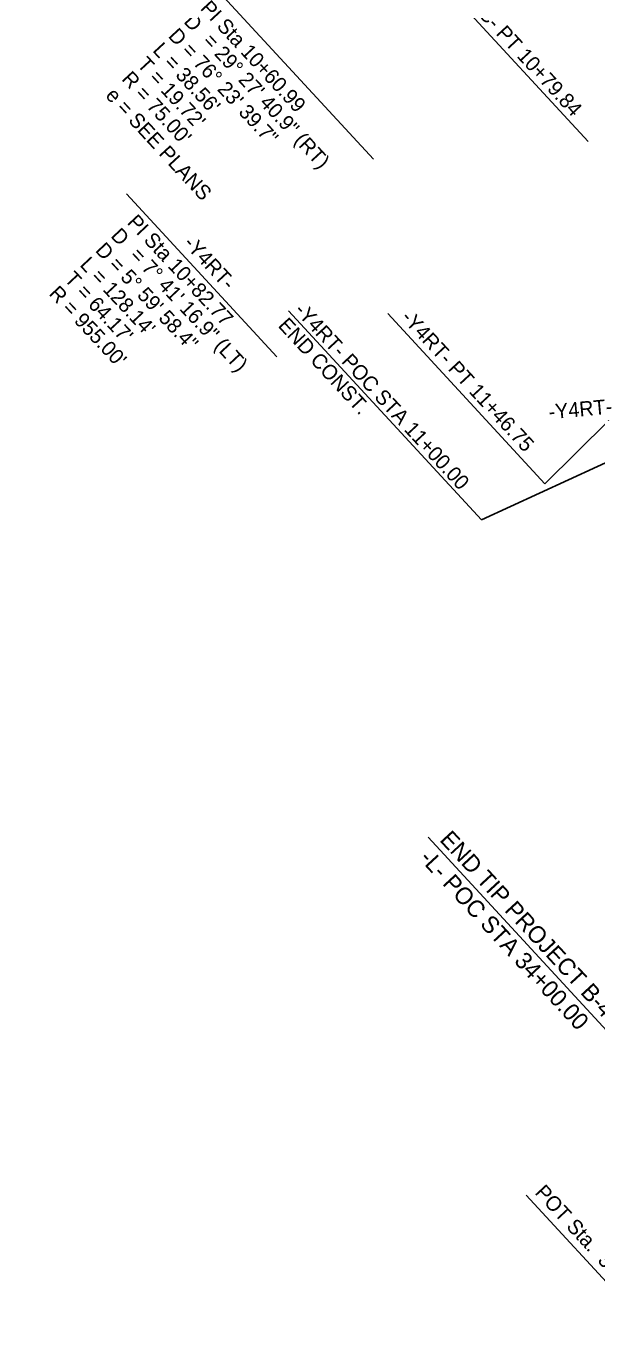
# Model space of a CAD drawing. Extents: x 1702862 to 1704514, y 793768 to 796215.
# Drawn here: x 1703564 to 1703834, y 793768 to 794386 of the extents above; entities that cross this region are included whole.
import ezdxf

# ---------------------------------------------------------------- set-up
doc = ezdxf.new("R2010")
doc.units = 0
for name, color, linetype in [('Exist Horizontal Alignment Curve and Spiral Data', 7, 'Continuous'), ('Exist Horizontal Alignment Station Label', 7, 'Continuous'), ('Prop DSN Text', 7, 'Continuous'), ('Prop EOT', 7, 'Continuous'), ('Prop Horizontal Alignment', 7, 'Continuous'), ('Prop Horizontal Alignment Curve and Spiral Data', 7, 'Continuous'), ('Prop Horizontal Alignment Direction Label', 7, 'Continuous'), ('Prop Horizontal Alignment Station Label', 7, 'Continuous'), ('Prop Lane Lines', 7, 'Continuous'), ('Prop Leader Line Medium', 7, 'Continuous')]:
    doc.layers.add(name, color=color, linetype=linetype)

msp = doc.modelspace()

# ---------------------------------------------------------------- linework, layer by layer
at = {"layer": 'Exist Horizontal Alignment Curve and Spiral Data'}
msp.add_line((1703611.73, 794306.9), (1703682.73, 794229.98), dxfattribs=at)
at = {"layer": 'Exist Horizontal Alignment Station Label'}
for p, q in [((1703735.18, 794250.31), (1703809.32, 794169.99)), ((1703809.32, 794169.99), (1703839.67, 794199.79))]:
    msp.add_line(p, q, dxfattribs=at)
at = {"layer": 'Prop EOT'}
msp.add_arc((1702989.11, 794124.65), 1018, 14.75888, 42.70907, dxfattribs=at)
at = {"layer": 'Prop Horizontal Alignment'}
msp.add_arc((1702989.11, 794124.65), 1000, 351.25916, 42.70907, dxfattribs=at)
at = {"layer": 'Prop Horizontal Alignment Curve and Spiral Data'}
for p, q in [((1703564.23, 794501.06), (1703728.41, 794323.2)), ((1703754.16, 794413.63), (1703829.87, 794331.61))]:
    msp.add_line(p, q, dxfattribs=at)
at = {"layer": 'Prop Horizontal Alignment Station Label'}
msp.add_line((1703800.56, 793833.92), (1703861.43, 793767.97), dxfattribs=at)
at = {"layer": 'Prop Lane Lines'}
for radius, start in [(1006, 0.00687), (994, 359.40932), (980, 359.40932)]:
    msp.add_arc((1702989.11, 794124.65), radius, start, 42.70907, dxfattribs=at)
at = {"layer": 'Prop Leader Line Medium'}
for p, q in [((1703688.26, 794251.68), (1703779.4, 794152.94)), ((1703886.36, 794202.16), (1703779.4, 794152.94)), ((1703754.24, 794003.01), (1703866.27, 793881.64))]:
    msp.add_line(p, q, dxfattribs=at)

# ---------------------------------------------------------------- texts
at = {"layer": 'Exist Horizontal Alignment Curve and Spiral Data'}
for s, rotation, p in [('PI Sta 10+82.77', 313.05007, (1703611.6, 794293.09)), ('D', 313.05007, (1703603.83, 794286.76)), ('D = 5%%d 59\' 58.4"', 313.05007, (1703596.52, 794279.93)), ('-Y4RT-', 312.70907, (1703638.2, 794283.16)), ("L = 128.14'", 313.05007, (1703589.22, 794273.11)), ('= 7%%d 41\' 16.9" (LT)', 313.05007, (1703612.82, 794277.57)), ("T = 64.17'", 313.05007, (1703581.91, 794266.28)), ("R = 955.00'", 313.05007, (1703574.6, 794259.45))]:
    msp.add_text(s, height=7, rotation=rotation, dxfattribs=at).set_placement(p)
at = {"layer": 'Exist Horizontal Alignment Station Label'}
msp.add_text('-Y4RT- PT 11+46.75', height=7, rotation=312.70907, dxfattribs=at).set_placement((1703741.05, 794248.08))
at = {"layer": 'Prop DSN Text'}
for s, height, p in [('-Y4RT- POC STA 11+00.00', 7, (1703690.63, 794251.52)), ('END CONST.', 7, (1703682.92, 794244.4)), ('END TIP PROJECT B-4760', 8, (1703759.29, 794001.5)), ('-L- POC STA 34+00.00', 8, (1703749.74, 793992.69))]:
    msp.add_text(s, height=height, rotation=312.70907, dxfattribs=at).set_placement(p)
at = {"layer": 'Prop Horizontal Alignment Curve and Spiral Data'}
for s, p in [('PI Sta 10+60.99', (1703646.15, 794394.26)), ('D', (1703638.35, 794387.97)), ('D = 76%%d 23\' 39.7"', (1703631, 794381.19)), ("L = 38.56'", (1703623.65, 794374.4)), ('= 29%%d 27\' 40.9" (RT)', (1703647.28, 794378.73)), ("T = 19.72'", (1703616.3, 794367.62)), ("R = 75.00'", (1703608.96, 794360.84)), ('e = SEE PLANS', (1703601.35, 794353.03))]:
    msp.add_text(s, height=7, rotation=312.70907, dxfattribs=at).set_placement(p)
at = {"layer": 'Prop Horizontal Alignment Direction Label'}
msp.add_text('-Y4RT-', height=7, rotation=5.16296, dxfattribs=at).set_placement((1703811.43, 794200.4))
at = {"layer": 'Prop Horizontal Alignment Station Label'}
for s, p in [('-LOOPC- PT 10+79.84', (1703757.71, 794413.01)), ('POT Sta.  35+96.17', (1703804.31, 793834.88))]:
    msp.add_text(s, height=7, rotation=312.70907, dxfattribs=at).set_placement(p)

doc.saveas('drawing.dxf')
